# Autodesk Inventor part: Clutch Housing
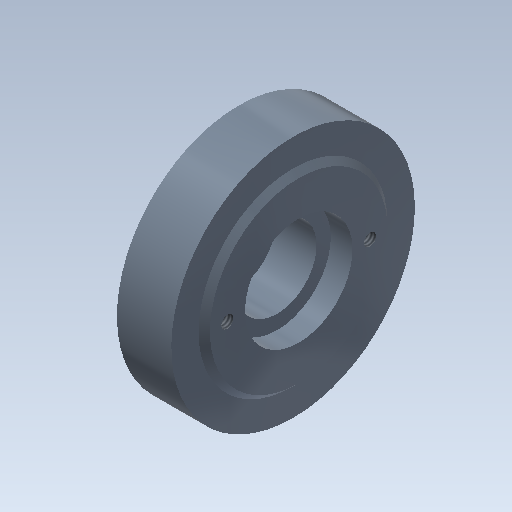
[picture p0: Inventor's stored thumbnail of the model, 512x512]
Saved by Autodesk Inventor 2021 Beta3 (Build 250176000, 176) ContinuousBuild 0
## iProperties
Created: 2012-08
Part Number: Clutch Housing
Material: Stainless Steel, 440C
Document SubType Name: Modeling
Designer: John
Density: 7.75 g/cm^3
Mass: 19.0964 g
Surface Area: 27.3425 cm^2
Volume: 2.46405 cm^3
Appearance: Steel Blue
Author: John
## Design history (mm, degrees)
sketch "Sketch1"
  geometry: C1 r 14.224 at (0, 0); 1 further point
  constraints: 1 centre point, 1 coincident
  dimensions: "d0" = 28.448 diameter of C1
extrude "Extrusion1" new body sketch "Sketch1" distance "d1" = 9.9822; taper "d2" = 0 deg
sketch "Sketch4"
  geometry: C1 r 14.224 at (0, 0) reference; C2 r 10.376 at (0, 0)
  constraints: 1 centre point, 1 coincident
  dimensions: "d10" = 20.7518 diameter of C2
extrude "Extrusion4" cut sketch "Sketch4" distance "d11" = 0.6604; taper "d12" = 0 deg
chamfer "Chamfer1" distance "d13" = 0.6604; stored, may be unused: second distance "d14" = 3.175, angle "d15" = 45 deg
sketch "Sketch5"
  geometry: C1 r 14.224 at (0, 0) reference; C2 r 5.461 at (0, 0)
  constraints: 1 centre point, 1 coincident
  dimensions: "d16" = 10.922 diameter of C2
extrude "Extrusion5" cut sketch "Sketch5" distance "d17" = 2.9718; taper "d18" = 0 deg
sketch "Sketch6"
  geometry: C1 r 5.461 at (0, 0) reference; C2 r 14.224 at (0, 0) reference; C3 r 13.018 at (0, 0)
  constraints: 1 centre point, 1 coincident
  dimensions: "d19" = 26.035 diameter of C3
extrude "Extrusion6" cut sketch "Sketch6" distance "d20" = 2.5654; taper "d21" = 0 deg
sketch "Sketch7"
  geometry: C1 r 13.018 at (0, 0) reference; C2 r 10.477 at (0, 0)
  constraints: 1 centre point, 1 coincident
  dimensions: "d22" = 20.955 diameter of C2
extrude "Extrusion7" cut sketch "Sketch7" distance "d23" = 1.3716; taper "d24" = 0 deg
sketch "Sketch8"
  geometry: C1 r 5.461 at (0, 0) reference
hole "Hole1" sketch "Sketch8" at (0, 0) diameter "d25" = 5.08; stored, may be unused: countersink angle "d29" = 82 deg, drill point angle "d31" = 118 deg; dims "d26" = 19.05, "d27" = 9.525, "d28" = 6.35, "d30" = 25.4
sketch "Sketch9"
  geometry: C1 r 2.54 at (0, 0) reference; C2 r 10.376 at (0, 0) reference; C3 r 6.287 at (0, 0)
  constraints: 1 centre point, 1 coincident
  dimensions: "d32" = 12.573 diameter of C3
extrude "Extrusion8" cut sketch "Sketch9" distance "d33" = 2.54; taper "d34" = 0 deg
sketch "Sketch10"
  geometry: C1 r 10.376 at (0, 0) reference; C2 r 4.636 at (0, 0)
  constraints: 1 centre point, 1 coincident
  dimensions: "d35" = 9.271 diameter of C2
extrude "Extrusion9" cut sketch "Sketch10" distance "d36" = 7.3152; taper "d37" = 0 deg
sketch "Sketch11"
  geometry: L1 (0, -10.376)-(0, -6.287); L2 (0, -6.287)-(0, 0); L3 (0, 6.287)-(0, 0); L4 (0, 10.376)-(0, 6.287); A1 r 6.287 centre (0, 0) between (0, -6.287) and (0, -6.287) reference; A2 r 10.376 centre (0, 0) between (0, -10.376) and (0, 10.376) reference; 2 further points
  constraints: 8 end point, 5 point on circle, 4 collinear, 2 midpoint, 1 point on line, 1 vertical
hole "Hole2" sketch "Sketch11" at (0, -8.331), (0, 8.331) diameter "d38" = 1.4224; stored, may be unused: countersink angle "d42" = 82 deg, drill point angle "d44" = 118 deg; dims "d39" = 19.05, "d40" = 3.0226, "d41" = 6.35, "d43" = 25.4
body "Solid1"
